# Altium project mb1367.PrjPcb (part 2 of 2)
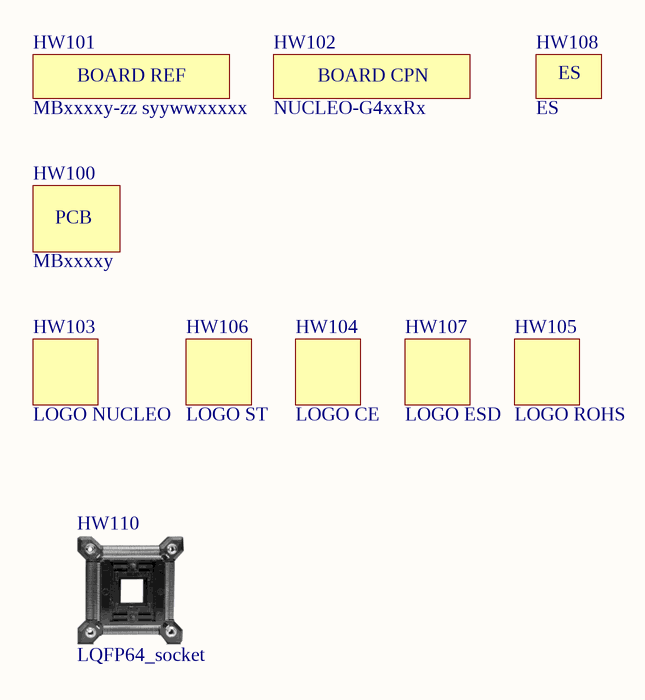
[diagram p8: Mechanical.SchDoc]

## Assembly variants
G474RE: not fitted C3 CN2 HW1 HW20 HW110 R6 SB8 SB10 SB12 SB14 SB18 SB20 SB21 SB22 SB24 SB27 SB28 SB29 SB32 SB34 SB37
G431RB: not fitted C3 CN2 HW1 HW20 HW110 R6 SB8 SB10 SB12 SB14 SB18 SB20 SB21 SB22 SB24 SB27 SB28 SB29 SB32 SB34 SB37
G491RE: not fitted C3 CN2 HW1 HW20 HW110 R6 SB8 SB10 SB12 SB14 SB18 SB20 SB21 SB22 SB24 SB27 SB28 SB29 SB32 SB34 SB37
WS: not fitted C3 CN2 HW1 HW20 R6 SB8 SB10 SB12 SB14 SB18 SB20 SB21 SB22 SB24 SB27 SB28 SB29 SB32 SB34 SB37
